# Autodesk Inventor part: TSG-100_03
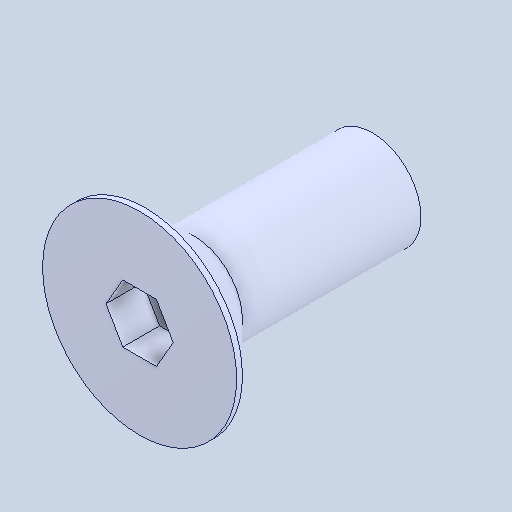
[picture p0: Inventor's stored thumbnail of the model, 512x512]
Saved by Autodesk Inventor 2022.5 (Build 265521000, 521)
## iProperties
Created: 2024-05
Part Number: TSG-100_03
Material: 一般
Document SubType Name: Modeling
Designer: ImaoCorp
Density: 1 g/cm^3
Appearance: 既定
Author: ImaoCorp
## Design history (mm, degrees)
feature "TSG-100_03"
node "ソリッド1"
